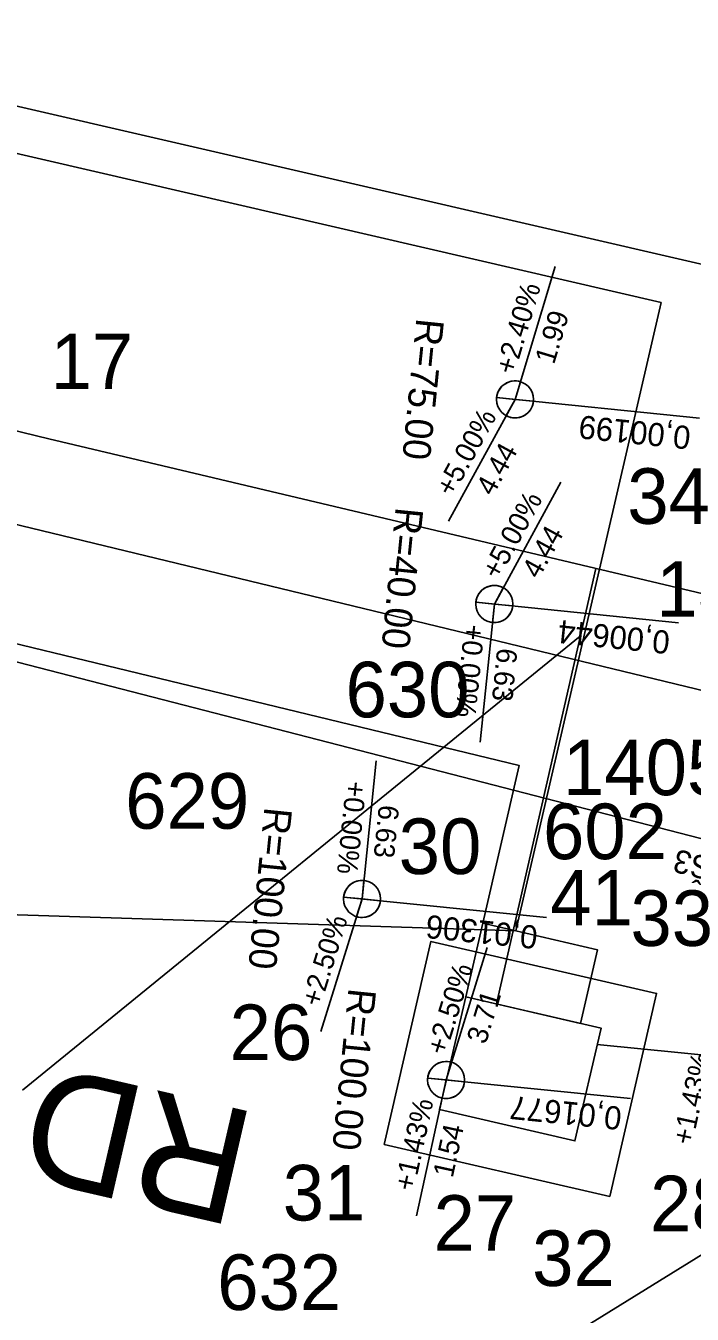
# Model space of a CAD drawing. Extents: x -748344 to -743169, y -1131966 to -1127091.
# Drawn here: x -747617.24 to -747602.85, y -1131717.22 to -1131689.39 of the extents above; entities that cross this region are included whole.
import ezdxf

# ---------------------------------------------------------------- set-up
doc = ezdxf.new("R2010")
doc.units = 0
for name, color, linetype in [('_RD', 7, 'Continuous'), ('_TRASA_vedení kabelu_CEZ', 7, 'Continuous'), ('_Zabezpečovací zařízení_trasa', 7, 'Continuous'), ('bublina_fialová_čára_tenká', 7, 'Continuous'), ('křížky', 7, 'Continuous'), ('Nový stav', 7, 'Continuous'), ('SKLONOVNIKY', 7, 'Continuous'), ('SMEROVE_A_VYSKOVE_VYROVNANI', 7, 'Continuous'), ('TRATIVOD_POP', 7, 'Continuous'), ('Vrstva 53', 7, 'Continuous'), ('Vrstva 60', 7, 'Continuous')]:
    doc.layers.add(name, color=color, linetype=linetype)

# ---------------------------------------------------------------- blocks, each defined once
blk = doc.blocks.new('POINT_DISPLAY')
blk.add_line((0, 0), (0, 0))
blk = doc.blocks.new('AeccTickCircle')
blk.add_circle((0, 0), 0.5)

msp = doc.modelspace()

# ---------------------------------------------------------------- linework, layer by layer
msp.add_lwpolyline([(-747607.376, -1131708.78), (-747606.588, -1131705.368), (-747647.265, -1131695.524)])
at = {"layer": '_RD'}
for points in [[(-747609.505, -1131713.555), (-747608.492, -1131709.17), (-747603.621, -1131710.295), (-747604.633, -1131714.68)], [(-747609.505, -1131713.555), (-747608.492, -1131709.17), (-747603.621, -1131710.295), (-747604.633, -1131714.68)], [(-747608.306, -1131712.805), (-747607.743, -1131710.369), (-747604.82, -1131711.045), (-747605.383, -1131713.48)], [(-747608.306, -1131712.805), (-747607.743, -1131710.369), (-747604.82, -1131711.045), (-747605.383, -1131713.48)]]:
    msp.add_lwpolyline(points, close=True, dxfattribs=at)
at = {"layer": '_TRASA_vedení kabelu_CEZ'}
msp.add_lwpolyline([(-747606.661, -1131708.945), (-747603.525, -1131695.366), (-747628.041, -1131689.704), (-747599.968, -1131653.349), (-747599.823, -1131650.348), (-747590.152, -1131609.621), (-747577.851, -1131574.826), (-747576.114, -1131566.001), (-747573.02, -1131550.257), (-747574.144, -1131533.397), (-747574.335, -1131530.458), (-747575.576, -1131507.342), (-747576.376, -1131492.518), (-747578.396, -1131453.504)], dxfattribs=at)
msp.add_lwpolyline([(-747607.376, -1131708.78), (-747604.899, -1131709.352), (-747605.267, -1131710.943), (-747607.743, -1131710.371)], close=True, dxfattribs=at)
at = {"layer": '_Zabezpečovací zařízení_trasa'}
for p, q in [((-747604.936, -1131701.113), (-747607.078, -1131710.523)), ((-747590.628, -1131712.828), (-747604.902, -1131711.398))]:
    msp.add_line(p, q, dxfattribs=at)
msp.add_lwpolyline([(-747299.39, -1131774.358), (-747312.964, -1131771.536), (-747335.194, -1131765.862), (-747431.496, -1131743.033), (-747485.589, -1131729.823), (-747529.872, -1131718.897), (-747616.745, -1131698.315), (-747822.016, -1131648.41), (-747861.482, -1131639.038), (-748013.304, -1131601.999), (-748116.903, -1131577.077), (-748210.219, -1131554.485), (-748277.301, -1131538.228)], dxfattribs=at)
at = {"layer": 'bublina_fialová_čára_tenká'}
msp.add_line((-747674.619, -1131706.761), (-747606.661, -1131708.945), dxfattribs=at)
at = {"layer": 'Nový stav'}
for p, q in [((-747605.27, -1131702.58), (-747617.314, -1131712.384)), ((-747589.393, -1131707.724), (-747611.929, -1131721.686))]:
    msp.add_line(p, q, dxfattribs=at)
at = {"layer": 'SKLONOVNIKY'}
for p, q in [((-747606.677, -1131697.463), (-747605.811, -1131694.59)), ((-747606.677, -1131697.463), (-747608.117, -1131700.095)), ((-747602.697, -1131697.866), (-747607.075, -1131697.422)), ((-747607.124, -1131701.883), (-747605.685, -1131699.251)), ((-747603.145, -1131702.286), (-747607.522, -1131701.843)), ((-747607.124, -1131701.883), (-747607.427, -1131704.868)), ((-747609.981, -1131708.254), (-747609.678, -1131705.27)), ((-747606.001, -1131708.657), (-747610.379, -1131708.214)), ((-747609.981, -1131708.254), (-747610.87, -1131711.12)), ((-747608.165, -1131712.165), (-747607.276, -1131709.3)), ((-747604.186, -1131712.568), (-747608.563, -1131712.125)), ((-747608.165, -1131712.165), (-747608.805, -1131715.096))]:
    msp.add_line(p, q, dxfattribs=at)
for points in [[(-747607.075, -1131697.422), (-747606.677, -1131697.463), (-747606.561, -1131697.08)], [(-747606.279, -1131697.503), (-747606.677, -1131697.463), (-747606.869, -1131697.814)], [(-747607.522, -1131701.843), (-747607.124, -1131701.883), (-747606.932, -1131701.532)], [(-747606.726, -1131701.924), (-747607.124, -1131701.883), (-747607.165, -1131702.281)], [(-747610.379, -1131708.214), (-747609.981, -1131708.254), (-747609.94, -1131707.856)], [(-747609.583, -1131708.295), (-747609.981, -1131708.254), (-747610.099, -1131708.636)], [(-747608.563, -1131712.125), (-747608.165, -1131712.165), (-747608.047, -1131711.783)], [(-747607.767, -1131712.205), (-747608.165, -1131712.165), (-747608.251, -1131712.556)]]:
    msp.add_lwpolyline(points, dxfattribs=at)
for centre, start, end in [((-747606.677, -1131697.463), 73.2181, 174.2192), ((-747606.677, -1131697.463), 241.32, 354.2192), ((-747607.124, -1131701.883), 61.32, 174.2192), ((-747607.124, -1131701.883), 264.2192, 354.2192), ((-747609.981, -1131708.254), 84.2192, 174.2192), ((-747609.981, -1131708.254), 252.7625, 354.2192), ((-747608.165, -1131712.165), 72.7625, 174.2192), ((-747608.165, -1131712.165), 257.6852, 354.2192)]:
    msp.add_arc(centre, 0.4, start, end, dxfattribs=at)
at = {"layer": 'SMEROVE_A_VYSKOVE_VYROVNANI'}
msp.add_lwpolyline([(-747648.511, -1131692.65), (-747601.65, -1131703.991)], dxfattribs=at)
at = {"layer": 'Vrstva 53'}
for points in [[(-747844.03, -1131636.81), (-747806.67, -1131645.86), (-747772.35, -1131654.05), (-747751.97, -1131658.69), (-747733.77, -1131662.83), (-747698.69, -1131671.28), (-747680.04, -1131675.66), (-747660.92, -1131680.14), (-747626.3, -1131689.08), (-747600.45, -1131695.05), (-747601.8, -1131707.17)], [(-747601.8, -1131707.17), (-747633.7, -1131698.94), (-747668.66, -1131690.61), (-747778.64, -1131662.29), (-747812.97, -1131653.81), (-747849.57, -1131644.15)]]:
    msp.add_lwpolyline(points, dxfattribs=at)
at = {"layer": 'Vrstva 60'}
for p, q in [((-747603.525, -1131695.366), (-747603.525, -1131695.366)), ((-747616.745, -1131698.315), (-747616.745, -1131698.315)), ((-747604.936, -1131701.113), (-747604.936, -1131701.113)), ((-747603.262, -1131703.6), (-747603.262, -1131703.6)), ((-747606.588, -1131705.368), (-747606.588, -1131705.368)), ((-747607.376, -1131708.78), (-747607.376, -1131708.78)), ((-747606.661, -1131708.945), (-747606.661, -1131708.945)), ((-747608.492, -1131709.17), (-747608.492, -1131709.17)), ((-747604.899, -1131709.352), (-747604.899, -1131709.352)), ((-747607.743, -1131710.369), (-747607.743, -1131710.369)), ((-747607.743, -1131710.37), (-747607.743, -1131710.37)), ((-747603.621, -1131710.295), (-747603.621, -1131710.295)), ((-747607.078, -1131710.523), (-747607.078, -1131710.523)), ((-747605.267, -1131710.943), (-747605.267, -1131710.943)), ((-747604.82, -1131711.045), (-747604.82, -1131711.045)), ((-747604.902, -1131711.398), (-747604.902, -1131711.398)), ((-747608.306, -1131712.805), (-747608.306, -1131712.805)), ((-747605.383, -1131713.48), (-747605.383, -1131713.48)), ((-747609.505, -1131713.555), (-747609.505, -1131713.555)), ((-747604.633, -1131714.68), (-747604.633, -1131714.68))]:
    msp.add_line(p, q, dxfattribs=at)

# ---------------------------------------------------------------- block references
at = {"layer": 'křížky', "xscale": 10, "yscale": 10, "rotation": 61.14491455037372}
for p in [(-747603.525, -1131695.366), (-747616.745, -1131698.315), (-747604.936, -1131701.113), (-747603.262, -1131703.6), (-747606.588, -1131705.368), (-747607.376, -1131708.78), (-747606.661, -1131708.945), (-747608.492, -1131709.17), (-747604.899, -1131709.352), (-747607.743, -1131710.369), (-747607.743, -1131710.37), (-747603.621, -1131710.295), (-747607.078, -1131710.523), (-747605.267, -1131710.943), (-747604.82, -1131711.045), (-747604.902, -1131711.398), (-747608.306, -1131712.805), (-747605.383, -1131713.48), (-747609.505, -1131713.555), (-747604.633, -1131714.68)]:
    msp.add_blockref('POINT_DISPLAY', p, dxfattribs=at)
at = {"layer": 'SKLONOVNIKY', "xscale": 0.8000000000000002, "yscale": -0.8, "rotation": 174.2192274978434}
for p in [(-747606.677, -1131697.463), (-747607.124, -1131701.883), (-747609.981, -1131708.254), (-747608.165, -1131712.165)]:
    msp.add_blockref('AeccTickCircle', p, dxfattribs=at)

# ---------------------------------------------------------------- texts
at = {"layer": '_RD'}
msp.add_text('RD', height=2.5, rotation=166.9979, dxfattribs=at).set_placement((-747612.203, -1131712.894))
at = {"layer": 'SKLONOVNIKY'}
for s, height, rotation, p in [('+2.40%', 0.44, 73.2181, (-747606.696, -1131696.95)), ('1.99', 0.44, 73.2181, (-747605.836, -1131696.725)), ('R=75.00', 0.6, 264.2192, (-747608.806, -1131695.696)), ('+5.00%', 0.44, 61.32, (-747608.029, -1131699.589)), ('0,00199', 0.5, 174.2192, (-747602.866, -1131698.048)), ('4.44', 0.44, 61.32, (-747607.157, -1131699.57)), ('+5.00%', 0.44, 61.32, (-747607.037, -1131701.378)), ('R=40.00', 0.6, 264.2192, (-747609.253, -1131699.777)), ('4.44', 0.44, 61.32, (-747606.165, -1131701.359)), ('+0.00%', 0.44, 264.2192, (-747607.768, -1131702.306)), ('0,00644', 0.5, 174.2192, (-747603.314, -1131702.469)), ('6.63', 0.44, 264.2192, (-747607.061, -1131702.822)), ('+0.00%', 0.44, 264.2192, (-747610.322, -1131705.693)), ('6.63', 0.44, 264.2192, (-747609.615, -1131706.208)), ('R=100.00', 0.6, 264.2192, (-747612.086, -1131706.256)), ('+2.50%', 0.44, 72.7625, (-747610.884, -1131710.607)), ('0,01306', 0.5, 174.2192, (-747606.17, -1131708.84)), ('+2.50%', 0.44, 72.7625, (-747608.18, -1131711.652)), ('R=100.00', 0.6, 264.2192, (-747610.271, -1131710.167)), ('3.71', 0.44, 72.7625, (-747607.312, -1131711.412)), ('+1.43%', 0.44, 77.6852, (-747602.856, -1131713.591)), ('+1.43%', 0.44, 77.6852, (-747608.864, -1131714.586)), ('0,01677', 0.5, 174.2192, (-747604.355, -1131712.75)), ('1.54', 0.44, 77.6852, (-747608.024, -1131714.294))]:
    msp.add_text(s, height=height, rotation=rotation, dxfattribs=at).set_placement(p)
at = {"layer": 'TRATIVOD_POP'}
msp.add_text('Š3', height=0.5, rotation=166, dxfattribs=at).set_placement((-747602.386, -1131707.37))
at = {"layer": 'Vrstva 60'}
for s, p in [('17', (-747616.707, -1131697.241)), ('34', (-747604.253, -1131700.151)), ('1303', (-747603.627, -1131702.158)), ('630', (-747610.338, -1131704.331)), ('1405', (-747605.642, -1131706.012)), ('629', (-747615.095, -1131706.737)), ('602', (-747606.073, -1131707.394)), ('30', (-747609.19, -1131707.716)), ('41', (-747605.918, -1131708.826)), ('33', (-747604.185, -1131709.269)), ('26', (-747612.841, -1131711.735)), ('31', (-747611.693, -1131715.2)), ('28', (-747603.761, -1131715.432)), ('27', (-747608.437, -1131715.854)), ('32', (-747606.308, -1131716.615)), ('632', (-747613.108, -1131717.133))]:
    msp.add_text(s, height=1.2, dxfattribs=at).set_placement(p)

doc.saveas('drawing.dxf')
